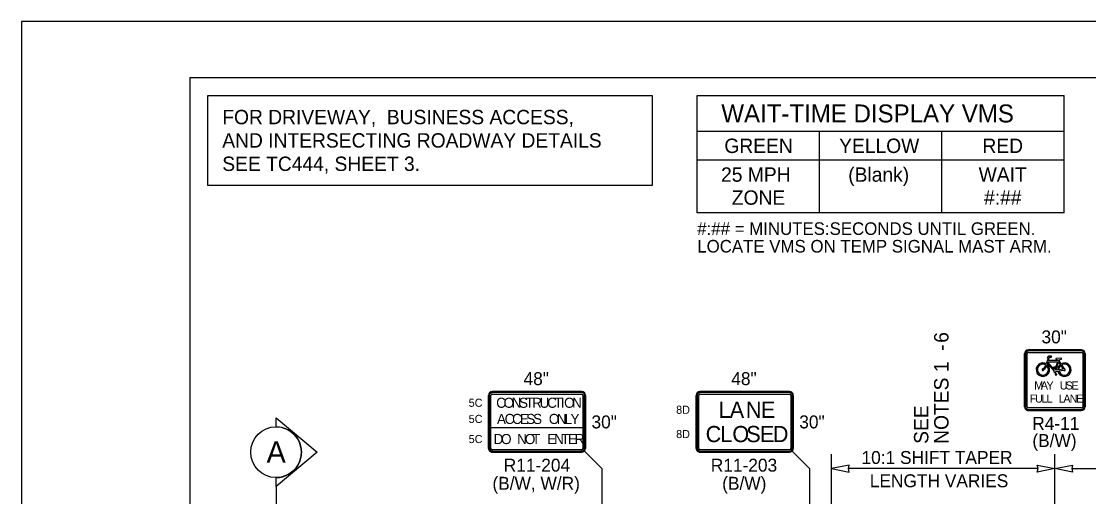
# Model space of a CAD drawing. Extents: x 99976 to 100136, y 99905 to 100011.
# Drawn here: x 100019.06 to 100025, y 99948.04 to 99950.69 of the extents above; entities that cross this region are included whole.
import ezdxf

# ---------------------------------------------------------------- set-up
doc = ezdxf.new("R2010")
doc.units = 0
for name, color, linetype in [('SH_GI_PlotLimits', 7, 'Continuous'), ('SH_GI_SheetBorder', 7, 'Continuous'), ('SH_TI_Tables', 7, 'Continuous'), ('SH_TI_WZSectionCut', 7, 'Continuous'), ('TR_SN_ConstructionSigns', 7, 'Continuous'), ('TR_WZ_PortableChangeMessageSign', 7, 'Continuous'), ('TR_WZ_WorkZoneDetails', 7, 'Continuous'), ('TR_WZ_WorkZoneTextCurrent', 7, 'Continuous')]:
    doc.layers.add(name, color=color, linetype=linetype)

msp = doc.modelspace()

# ---------------------------------------------------------------- linework, layer by layer
at = {"layer": 'SH_GI_PlotLimits'}
msp.add_lwpolyline([(100019.0625, 99939.6875), (100036.0625, 99939.6875), (100036.0625, 99950.6875), (100019.0625, 99950.6875)], close=True, dxfattribs=at)
at = {"layer": 'SH_GI_SheetBorder'}
for q in [(100020, 99940), (100035.75, 99950.375)]:
    msp.add_line((100020, 99950.375), q, dxfattribs=at)
at = {"layer": 'SH_TI_Tables'}
msp.add_lwpolyline([(100020.1, 99950.275), (100022.5718, 99950.275), (100022.5718, 99949.775), (100020.1, 99949.775)], close=True, dxfattribs=at)
at = {"layer": 'SH_TI_WZSectionCut'}
for p, q in [((100020.4793, 99948.4317), (100020.4793, 99948.4816)), ((100020.4793, 99948.4816), (100020.7074, 99948.2904)), ((100020.7074, 99948.2904), (100020.4793, 99948.0993)), ((100020.4793, 99948.0993), (100020.4793, 99948.1492)), ((100020.4793, 99948.0993), (100020.4793, 99946.0193))]:
    msp.add_line(p, q, dxfattribs=at)
msp.add_circle((100020.4793, 99948.2904), 0.1412, dxfattribs=at)
msp.add_arc((100020.4793, 99948.2904), 0.1412, 269.99779, 90.00221, dxfattribs=at)
at = {"layer": 'TR_SN_ConstructionSigns'}
for p, q in [((100024.6423, 99948.5435), (100024.6423, 99948.8388)), ((100024.6423, 99948.8388), (100024.6423, 99948.5435)), ((100024.6423, 99948.8388), (100024.6423, 99948.5435)), ((100024.648, 99948.8388), (100024.648, 99948.5435)), ((100024.6564, 99948.5435), (100024.6564, 99948.8388)), ((100024.6634, 99948.8599), (100024.9588, 99948.8599)), ((100024.9588, 99948.8599), (100024.6634, 99948.8599)), ((100024.9588, 99948.8599), (100024.6634, 99948.8599)), ((100024.9588, 99948.8543), (100024.6634, 99948.8543)), ((100024.6634, 99948.8458), (100024.9588, 99948.8458)), ((100024.7751, 99948.8247), (100024.7681, 99948.8178)), ((100024.7916, 99948.8247), (100024.7751, 99948.8247)), ((100024.7916, 99948.8192), (100024.7916, 99948.8247)), ((100024.9658, 99948.8388), (100024.9658, 99948.5435)), ((100024.9742, 99948.5435), (100024.9742, 99948.8388)), ((100024.9798, 99948.8388), (100024.9798, 99948.5435)), ((100024.9798, 99948.5435), (100024.9798, 99948.8388)), ((100024.9798, 99948.5435), (100024.9798, 99948.8388)), ((100024.7728, 99948.8131), (100024.7624, 99948.782)), ((100024.7676, 99948.7784), (100024.7653, 99948.7717)), ((100024.7676, 99948.7784), (100024.7692, 99948.7831)), ((100024.7681, 99948.8178), (100024.7728, 99948.8131)), ((100024.7692, 99948.7831), (100024.7715, 99948.7902)), ((100024.7692, 99948.7831), (100024.8058, 99948.7433)), ((100024.7715, 99948.7902), (100024.7728, 99948.794)), ((100024.8062, 99948.7526), (100024.7715, 99948.7902)), ((100024.7728, 99948.794), (100024.8254, 99948.794)), ((100024.775, 99948.8006), (100024.7792, 99948.8131)), ((100024.8276, 99948.8006), (100024.775, 99948.8006)), ((100024.7752, 99948.8171), (100024.7774, 99948.8192)), ((100024.7792, 99948.8131), (100024.7752, 99948.8171)), ((100024.7774, 99948.8192), (100024.7916, 99948.8192)), ((100024.8115, 99948.7633), (100024.8027, 99948.7633)), ((100024.8254, 99948.794), (100024.811, 99948.7507)), ((100024.8115, 99948.76), (100024.8115, 99948.7633)), ((100024.8164, 99948.7462), (100024.8312, 99948.7904)), ((100024.8435, 99948.8135), (100024.8186, 99948.8118)), ((100024.8288, 99948.804), (100024.8276, 99948.8006)), ((100024.8338, 99948.7983), (100024.8312, 99948.7904)), ((100024.8312, 99948.7904), (100024.8396, 99948.778)), ((100024.8338, 99948.7983), (100024.8357, 99948.8041)), ((100024.845, 99948.7818), (100024.8338, 99948.7983)), ((100024.8396, 99948.778), (100024.8433, 99948.7725)), ((100024.8433, 99948.7725), (100024.8571, 99948.7522)), ((100024.8636, 99948.7544), (100024.8487, 99948.7763)), ((100024.8049, 99948.76), (100024.8062, 99948.7526)), ((100024.811, 99948.7507), (100024.8093, 99948.76)), ((100024.8093, 99948.76), (100024.8115, 99948.76)), ((100024.8101, 99948.7352), (100024.8137, 99948.7244)), ((100024.8137, 99948.7244), (100024.8119, 99948.7244)), ((100024.8119, 99948.7244), (100024.8119, 99948.7211)), ((100024.8119, 99948.7211), (100024.8207, 99948.7211)), ((100024.8183, 99948.7244), (100024.8143, 99948.7366)), ((100024.816, 99948.7395), (100024.8273, 99948.7411)), ((100024.8264, 99948.7477), (100024.8164, 99948.7462)), ((100024.8207, 99948.7244), (100024.8183, 99948.7244)), ((100024.8207, 99948.7211), (100024.8207, 99948.7244)), ((100024.8273, 99948.7411), (100024.8338, 99948.7421)), ((100024.8571, 99948.7522), (100024.8329, 99948.7486)), ((100024.8338, 99948.7421), (100024.8601, 99948.746)), ((100021.6602, 99948.3112), (100021.6602, 99948.6065)), ((100021.6602, 99948.6065), (100021.6602, 99948.3112)), ((100021.6602, 99948.6065), (100021.6602, 99948.3112)), ((100021.6659, 99948.6065), (100021.6659, 99948.3112)), ((100021.6743, 99948.3112), (100021.6743, 99948.6065)), ((100021.6813, 99948.6276), (100022.1792, 99948.6276)), ((100022.1792, 99948.6276), (100021.6813, 99948.6276)), ((100022.1792, 99948.6276), (100021.6813, 99948.6276)), ((100022.1792, 99948.622), (100021.6813, 99948.622)), ((100021.6813, 99948.6135), (100022.1792, 99948.6135)), ((100022.1862, 99948.6065), (100022.1862, 99948.3112)), ((100022.1946, 99948.3112), (100022.1946, 99948.6065)), ((100022.2002, 99948.6065), (100022.2002, 99948.3112)), ((100022.2002, 99948.3112), (100022.2002, 99948.6065)), ((100022.2002, 99948.3112), (100022.2002, 99948.6065)), ((100022.8159, 99948.3112), (100022.8159, 99948.6065)), ((100022.8159, 99948.6065), (100022.8159, 99948.3112)), ((100022.8159, 99948.6065), (100022.8159, 99948.3112)), ((100022.8215, 99948.6065), (100022.8215, 99948.3112)), ((100022.8299, 99948.3112), (100022.8299, 99948.6065)), ((100022.8369, 99948.6276), (100023.3348, 99948.6276)), ((100023.3348, 99948.6276), (100022.8369, 99948.6276)), ((100023.3348, 99948.6276), (100022.8369, 99948.6276)), ((100023.3348, 99948.622), (100022.8369, 99948.622)), ((100022.8369, 99948.6135), (100023.3348, 99948.6135)), ((100023.3418, 99948.6065), (100023.3418, 99948.3112)), ((100023.3502, 99948.3112), (100023.3502, 99948.6065)), ((100023.3559, 99948.6065), (100023.3559, 99948.3112)), ((100023.3559, 99948.3112), (100023.3559, 99948.6065)), ((100023.3559, 99948.3112), (100023.3559, 99948.6065)), ((100024.9588, 99948.5364), (100024.6634, 99948.5364)), ((100024.6634, 99948.528), (100024.9588, 99948.528)), ((100024.9588, 99948.5224), (100024.6634, 99948.5224)), ((100024.6634, 99948.5224), (100024.9588, 99948.5224)), ((100024.6634, 99948.5224), (100024.9588, 99948.5224)), ((100022.2002, 99948.4251), (100021.6602, 99948.4251)), ((100021.6602, 99948.4251), (100021.6602, 99948.3112)), ((100021.6659, 99948.4251), (100021.6659, 99948.3112)), ((100021.6743, 99948.4251), (100021.6659, 99948.4251)), ((100021.6743, 99948.3112), (100021.6743, 99948.4251)), ((100022.1946, 99948.4251), (100022.1862, 99948.4251)), ((100022.1862, 99948.4251), (100022.1862, 99948.3112)), ((100022.1946, 99948.3112), (100022.1946, 99948.4251)), ((100022.2002, 99948.3112), (100022.2002, 99948.4251)), ((100021.6743, 99948.3112), (100021.6659, 99948.3112)), ((100021.6659, 99948.3112), (100021.6743, 99948.3112)), ((100022.1792, 99948.3042), (100021.6813, 99948.3042)), ((100022.1792, 99948.3042), (100021.6813, 99948.3042)), ((100021.6813, 99948.3042), (100021.6813, 99948.2957)), ((100021.6813, 99948.2957), (100021.6813, 99948.3042)), ((100021.6813, 99948.2957), (100022.1792, 99948.2957)), ((100021.6813, 99948.2957), (100022.1792, 99948.2957)), ((100022.1792, 99948.2901), (100021.6813, 99948.2901)), ((100021.6813, 99948.2901), (100022.1792, 99948.2901)), ((100021.6813, 99948.2901), (100022.1792, 99948.2901)), ((100021.6813, 99948.2901), (100022.1792, 99948.2901)), ((100022.1792, 99948.3042), (100022.1792, 99948.2957)), ((100022.1792, 99948.2957), (100022.1792, 99948.3042)), ((100022.1862, 99948.3112), (100022.1946, 99948.3112)), ((100022.1946, 99948.3112), (100022.1862, 99948.3112)), ((100023.3348, 99948.3042), (100022.8369, 99948.3042)), ((100022.8369, 99948.2957), (100023.3348, 99948.2957)), ((100023.3348, 99948.2901), (100022.8369, 99948.2901)), ((100022.8369, 99948.2901), (100023.3348, 99948.2901)), ((100022.8369, 99948.2901), (100023.3348, 99948.2901))]:
    msp.add_line(p, q, dxfattribs=at)
msp.add_lwpolyline([(100024.8027, 99948.7633), (100024.8027, 99948.76), (100024.8049, 99948.76)], dxfattribs=at)
for centre, radius, start, end in [((100024.6634, 99948.8388), 0.0211, 90, 180), ((100024.6634, 99948.8388), 0.0211, 90, 180), ((100024.6634, 99948.8388), 0.0211, 90, 180), ((100024.6634, 99948.8388), 0.0155, 90, 180.00001), ((100024.6634, 99948.8388), 0.00703, 90, 180.00001), ((100024.9588, 99948.8388), 0.0211, 0, 90), ((100024.9588, 99948.8388), 0.0211, 0, 90), ((100024.9588, 99948.8388), 0.0211, 0, 90), ((100024.9588, 99948.8388), 0.0155, 0, 90), ((100024.9588, 99948.8388), 0.00703, 0, 90), ((100024.7441, 99948.7495), 0.0373, 60.55289, 50.86797), ((100024.7441, 99948.7495), 0.0307, 58.15317, 46.16486), ((100024.8186, 99948.8096), 0.00219, 89.38537, 243.68281), ((100024.8636, 99948.7495), 0.0373, 130.08889, 182.8379), ((100024.8636, 99948.7495), 0.0373, 192.96225, 119.96476), ((100024.8636, 99948.7495), 0.0307, 131.36164, 181.63591), ((100024.8636, 99948.7495), 0.0307, 193.937, 119.05981), ((100024.8438, 99948.8102), 0.00329, 294.55187, 96.41278), ((100024.7441, 99948.7495), 0.00493, 105.25697, 14.32327), ((100024.8106, 99948.7407), 0.00548, 151.17436, 264.85662), ((100024.8106, 99948.7407), 0.00548, 312.00533, 347.29322), ((100024.8636, 99948.7495), 0.00493, 225.10948, 90.46721), ((100021.6813, 99948.6065), 0.0211, 90, 180), ((100021.6813, 99948.6065), 0.0211, 90, 180), ((100021.6813, 99948.6065), 0.0211, 90, 180), ((100021.6813, 99948.6065), 0.0155, 90, 180.00001), ((100021.6813, 99948.6065), 0.00703, 90, 180.00001), ((100022.1792, 99948.6065), 0.0211, 0, 90), ((100022.1792, 99948.6065), 0.0211, 0, 90), ((100022.1792, 99948.6065), 0.0211, 0, 90), ((100022.1792, 99948.6065), 0.0155, 0, 90), ((100022.1792, 99948.6065), 0.00703, 0, 90), ((100022.8369, 99948.6065), 0.0211, 90, 180), ((100022.8369, 99948.6065), 0.0211, 90, 180), ((100022.8369, 99948.6065), 0.0211, 90, 180), ((100022.8369, 99948.6065), 0.0155, 90, 180.00001), ((100022.8369, 99948.6065), 0.00703, 90, 180.00001), ((100023.3348, 99948.6065), 0.0211, 0, 90), ((100023.3348, 99948.6065), 0.0211, 0, 90), ((100023.3348, 99948.6065), 0.0211, 0, 90), ((100023.3348, 99948.6065), 0.0155, 0, 90), ((100023.3348, 99948.6065), 0.00703, 0, 90), ((100024.6634, 99948.5435), 0.0211, 180, 270.00001), ((100024.6634, 99948.5435), 0.0211, 180, 270.00001), ((100024.6634, 99948.5435), 0.0211, 180, 270.00001), ((100024.6634, 99948.5435), 0.0155, 180.00001, 270), ((100024.6634, 99948.5435), 0.00703, 180.00001, 270), ((100024.9588, 99948.5435), 0.0211, 270.00001, 0.00001), ((100024.9588, 99948.5435), 0.0211, 270.00001, 0.00001), ((100024.9588, 99948.5435), 0.0155, 270, 0.00001), ((100024.9588, 99948.5435), 0.00703, 270, 0.00001), ((100024.9588, 99948.5435), 0.0211, 270.00001, 0.00001), ((100021.6813, 99948.3112), 0.0211, 180, 270.00001), ((100021.6813, 99948.3112), 0.0211, 180, 270.00001), ((100021.6813, 99948.3112), 0.0211, 180, 270.00001), ((100021.6813, 99948.3112), 0.0211, 180, 270.00001), ((100021.6813, 99948.3112), 0.0155, 180.00001, 270), ((100021.6813, 99948.3112), 0.0155, 180, 270.00001), ((100021.6813, 99948.3112), 0.00703, 180.00001, 270), ((100021.6813, 99948.3112), 0.00703, 180, 270.00001), ((100022.1792, 99948.3112), 0.0155, 270, 0.00001), ((100022.1792, 99948.3112), 0.00703, 270, 0.00001), ((100022.1792, 99948.3112), 0.0211, 270.00001, 0.00001), ((100022.1792, 99948.3112), 0.0211, 270.00001, 0.00001), ((100022.1792, 99948.3112), 0.0211, 270.00001, 0.00001), ((100022.1792, 99948.3112), 0.0211, 270.00001, 0.00001), ((100022.1792, 99948.3112), 0.0155, 270.00001, 0.00001), ((100022.1792, 99948.3112), 0.00703, 270.00001, 0.00001), ((100022.8369, 99948.3112), 0.0211, 180, 270.00001), ((100022.8369, 99948.3112), 0.0211, 180, 270.00001), ((100022.8369, 99948.3112), 0.0211, 180, 270.00001), ((100022.8369, 99948.3112), 0.0155, 180.00001, 270), ((100022.8369, 99948.3112), 0.00703, 180.00001, 270), ((100023.3348, 99948.3112), 0.0155, 270, 0.00001), ((100023.3348, 99948.3112), 0.00703, 270, 0.00001), ((100023.3348, 99948.3112), 0.0211, 270.00001, 0.00001), ((100023.3348, 99948.3112), 0.0211, 270.00001, 0.00001), ((100023.3348, 99948.3112), 0.0211, 270.00001, 0.00001)]:
    msp.add_arc(centre, radius, start, end, dxfattribs=at)
for centre, major_axis, ratio, start_param, end_param in [((100024.749, 99948.7702), (-0.0105, -0.0158), 0.413554, 0.494612, 2.170849), ((100024.749, 99948.7702), (-0.014, -0.021), 0.55814, 0.868091, 1.989998), ((100024.8317, 99948.8148), (-0.0186, 0), 0.588235, 0.686048, 1.410588), ((100024.8317, 99948.8148), (-0.0186, 0), 0.588235, 1.786993, 2.401245)]:
    msp.add_ellipse(centre, major_axis=major_axis, ratio=ratio, start_param=start_param, end_param=end_param, dxfattribs=at)
at = {"layer": 'TR_WZ_PortableChangeMessageSign'}
for p, q in [((100022.8218, 99950.275), (100024.8618, 99950.275)), ((100022.8218, 99949.6227), (100022.8218, 99950.275)), ((100024.8618, 99949.6227), (100024.8618, 99950.275)), ((100024.8618, 99950.075), (100022.8218, 99950.075)), ((100023.5018, 99949.6227), (100023.5018, 99950.075)), ((100024.1818, 99949.6227), (100024.1818, 99950.075)), ((100023.5018, 99949.915), (100022.8218, 99949.915)), ((100024.1818, 99949.915), (100023.5018, 99949.915)), ((100024.8618, 99949.915), (100024.1818, 99949.915)), ((100024.8618, 99949.6227), (100022.8218, 99949.6227))]:
    msp.add_line(p, q, dxfattribs=at)
at = {"layer": 'TR_WZ_WorkZoneDetails'}
for p, q in [((100022.1941, 99948.2963), (100022.291, 99948.1993)), ((100023.3497, 99948.2963), (100023.4466, 99948.1993)), ((100023.5692, 99946.2193), (100023.5692, 99948.2793)), ((100024.8112, 99947.804), (100024.8112, 99948.2793)), ((100022.291, 99948.1993), (100022.291, 99947.4289)), ((100023.4466, 99948.1993), (100023.4466, 99947.4289)), ((100024.7175, 99948.1993), (100023.6629, 99948.1993)), ((100024.9049, 99948.1993), (100025.4071, 99948.1993))]:
    msp.add_line(p, q, dxfattribs=at)
for points in [[(100023.5692, 99948.1993), (100023.6675, 99948.18), (100023.6629, 99948.1993), (100023.6675, 99948.2186)], [(100024.8112, 99948.1993), (100024.7129, 99948.18), (100024.7175, 99948.1993), (100024.7129, 99948.2186)], [(100024.8112, 99948.1993), (100024.9095, 99948.2186), (100024.9049, 99948.1993), (100024.9095, 99948.18)]]:
    msp.add_lwpolyline(points, close=True, dxfattribs=at)

# ---------------------------------------------------------------- texts
at = {"layer": 'SH_TI_Tables'}
for s, p in [('FOR DRIVEWAY,  BUSINESS ACCESS, ', (100020.18, 99950.115)), ('AND INTERSECTING ROADWAY DETAILS', (100020.18, 99949.985)), ('SEE TC444, SHEET 3.', (100020.18, 99949.855))]:
    msp.add_text(s, height=0.08, rotation=360, dxfattribs=at).set_placement(p)
at = {"layer": 'SH_TI_WZSectionCut'}
msp.add_text('A', height=0.12, rotation=359.99005, dxfattribs=at).set_placement((100020.4263, 99948.2313))
at = {"layer": 'TR_SN_ConstructionSigns'}
for s, p in [('30"', (100024.7363, 99948.8959)), ('48"', (100021.8555, 99948.6636)), ('48"', (100023.0111, 99948.6636)), ('30"', (100022.2335, 99948.4228)), ('30"', (100023.3891, 99948.4228)), ('R4-11', (100024.6848, 99948.4144)), ('(B/W)', (100024.6856, 99948.3193)), ('R11-204', (100021.7454, 99948.1821)), ('R11-203', (100022.8969, 99948.1821)), ('(B/W, W/R)', (100021.6825, 99948.0813)), ('(B/W)', (100022.9603, 99948.0813))]:
    msp.add_text(s, height=0.072, rotation=360, dxfattribs=at).set_placement(p)
for s, height, p in [('M', 0.045, (100024.6961, 99948.6391)), ('A', 0.045, (100024.7321, 99948.6391)), ('Y', 0.045, (100024.7636, 99948.6391)), ('U', 0.045, (100024.8374, 99948.6391)), ('S', 0.045, (100024.8703, 99948.6391)), ('E', 0.045, (100024.9031, 99948.6391)), ('5C', 0.045, (100021.5504, 99948.5429)), ('C', 0.0562, (100021.7033, 99948.5373)), ('O', 0.0562, (100021.7449, 99948.5373)), ('N', 0.0562, (100021.7893, 99948.5373)), ('S', 0.0562, (100021.8304, 99948.5373)), ('T', 0.0562, (100021.8669, 99948.5373)), ('R', 0.0562, (100021.9035, 99948.5373)), ('U', 0.0562, (100021.9446, 99948.5373)), ('C', 0.0562, (100021.9873, 99948.5373)), ('T', 0.0562, (100022.0256, 99948.5373)), ('I', 0.0562, (100022.0621, 99948.5373)), ('O', 0.0562, (100022.0813, 99948.5373)), ('N', 0.0562, (100022.1257, 99948.5373)), ('F', 0.045, (100024.6709, 99948.566)), ('U', 0.045, (100024.7002, 99948.566)), ('L', 0.045, (100024.7353, 99948.566)), ('L', 0.045, (100024.7645, 99948.566)), ('L', 0.045, (100024.8325, 99948.566)), ('A', 0.045, (100024.8581, 99948.566)), ('N', 0.045, (100024.8932, 99948.566)), ('E', 0.045, (100024.9283, 99948.566)), ('8D', 0.045, (100022.7043, 99948.5038)), ('L', 0.09, (100022.941, 99948.4813)), ('A', 0.09, (100023.0022, 99948.4813)), ('N', 0.09, (100023.0922, 99948.4813)), ('E', 0.09, (100023.175, 99948.4813)), ('5C', 0.045, (100021.5504, 99948.4529)), ('A', 0.0562, (100021.7078, 99948.4473)), ('C', 0.0562, (100021.7505, 99948.4473)), ('C', 0.0562, (100021.7921, 99948.4473)), ('E', 0.0562, (100021.8349, 99948.4473)), ('S', 0.0562, (100021.8703, 99948.4473)), ('S', 0.0562, (100021.9086, 99948.4473)), ('O', 0.0562, (100021.9963, 99948.4473)), ('N', 0.0562, (100022.0408, 99948.4473)), ('L', 0.0562, (100022.0846, 99948.4473)), ('Y', 0.0562, (100022.1167, 99948.4473)), ('8D', 0.045, (100022.7043, 99948.3688)), ('C', 0.09, (100022.8685, 99948.3463)), ('L', 0.09, (100022.9495, 99948.3463)), ('O', 0.09, (100023.017, 99948.3463)), ('S', 0.09, (100023.0944, 99948.3463)), ('E', 0.09, (100023.1709, 99948.3463)), ('D', 0.09, (100023.242, 99948.3463)), ('5C', 0.045, (100021.5504, 99948.341)), ('D', 0.0562, (100021.6889, 99948.3354)), ('O', 0.0562, (100021.7306, 99948.3354)), ('N', 0.0562, (100021.82, 99948.3354)), ('O', 0.0562, (100021.8627, 99948.3354)), ('T', 0.0562, (100021.9027, 99948.3354)), ('E', 0.0562, (100021.9876, 99948.3354)), ('N', 0.0562, (100022.0259, 99948.3354)), ('T', 0.0562, (100022.0652, 99948.3354)), ('E', 0.0562, (100022.1018, 99948.3354)), ('R', 0.0562, (100022.1401, 99948.3354))]:
    msp.add_text(s, height=height, dxfattribs=at).set_placement(p)
at = {"layer": 'TR_WZ_PortableChangeMessageSign'}
for s, height, p in [('WAIT-TIME DISPLAY VMS', 0.1, (100022.9556, 99950.125)), ('GREEN', 0.08, (100022.9724, 99949.955)), ('YELLOW', 0.08, (100023.6109, 99949.955)), ('RED', 0.08, (100024.4078, 99949.955)), ('25 MPH', 0.08, (100022.9542, 99949.795)), ('(Blank)', 0.08, (100023.6614, 99949.795)), ('WAIT', 0.08, (100024.3868, 99949.795)), ('ZONE', 0.08, (100023.0139, 99949.667)), ('#:##', 0.08, (100024.4169, 99949.667)), ('#:## = MINUTES:SECONDS UNTIL GREEN.', 0.07, (100022.8218, 99949.4993)), ('LOCATE VMS ON TEMP SIGNAL MAST ARM.', 0.07, (100022.8218, 99949.4013))]:
    msp.add_text(s, height=height, rotation=360, dxfattribs=at).set_placement(p)
at = {"layer": 'TR_WZ_WorkZoneTextCurrent'}
for s, p in [('6', (100024.2191, 99948.8988)), ('-', (100024.2191, 99948.8547)), ('NOTES 1', (100024.2191, 99948.3369)), ('SEE', (100024.1071, 99948.3369))]:
    msp.add_text(s, height=0.08, rotation=90, dxfattribs=at).set_placement(p)
for s, p in [('10:1 SHIFT TAPER', (100023.7352, 99948.2249)), ('LENGTH VARIES', (100023.7813, 99948.0953))]:
    msp.add_text(s, height=0.072, dxfattribs=at).set_placement(p)

doc.saveas('drawing.dxf')
